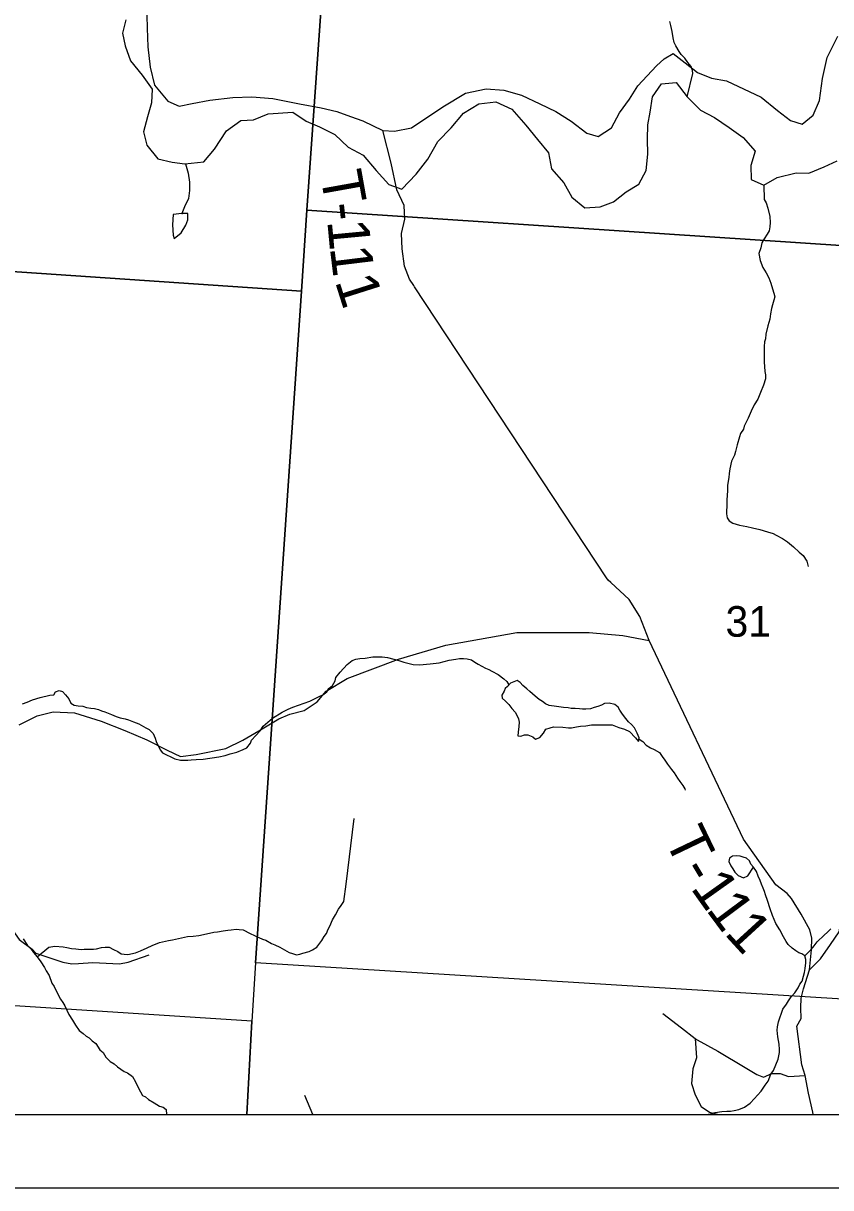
# Model space of a CAD drawing. Extents: x 0 to 34, y 0 to 22.
# Drawn here: x 6.168 to 7.274, y 14 to 15.594 of the extents above; entities that cross this region are included whole.
import ezdxf

# ---------------------------------------------------------------- set-up
doc = ezdxf.new("R2010")
doc.units = 0
for name, color, linetype in [('GM_X_Corporation', 7, 'Continuous'), ('GM_X_County_Road', 7, 'Continuous'), ('GM_X_Major_River', 7, 'Continuous'), ('GM_X_Minor_Lake', 7, 'Continuous'), ('GM_X_Minor_River', 7, 'Continuous'), ('GM_X_Section_Text', 7, 'Continuous'), ('GM_X_Township_Road', 7, 'Continuous'), ('GM_X_Township_Road_Text', 7, 'Continuous'), ('SH_Data', 7, 'Continuous')]:
    doc.layers.add(name, color=color, linetype=linetype)

msp = doc.modelspace()

# ---------------------------------------------------------------- linework, layer by layer
at = {"layer": 'GM_X_Corporation'}
for points in [[(3.3441, 14.1), (8.9, 14.1), (8.9, 20.9), (2.1, 20.9), (2.1, 16.1353), (2.1457, 16.065), (2.3447, 15.6926), (2.4297, 15.5215), (2.465, 15.4504), (2.4884, 15.4033), (2.5769, 15.2135), (2.7849, 14.8403), (2.8931, 14.6544), (3.0297, 14.4867), (3.1386, 14.3654), (3.228, 14.2415)], [(6.6272, 16.3394), (7.7202, 16.2762), (7.66, 15.265), (6.5568, 15.3381), (6.621, 16.2504)], [(5.4627, 14.1), (8.9, 14.1), (8.9, 16.2015), (7.873, 16.2628), (7.7162, 16.2721), (7.5782, 16.28), (6.6249, 16.3344), (6.6163, 16.2457), (5.9321, 16.289), (5.8351, 16.2952), (5.6497, 16.3069), (5.6022, 16.3258), (5.5809, 15.9822), (5.4893, 14.5091), (5.4833, 14.4122), (5.4763, 14.3006)], [(5.6072, 16.3154), (5.612, 16.3148), (6.621, 16.2504), (6.5568, 15.3381), (6.5491, 15.2271), (5.5415, 15.2956)], [(6.5568, 15.3381), (7.66, 15.265), (7.6002, 14.2387), (6.4864, 14.308), (6.5491, 15.2271)], [(5.5415, 15.2956), (6.5491, 15.2271), (6.4864, 14.308), (6.4814, 14.2281), (5.4795, 14.2928)], [(6.4745, 14.1), (7.5926, 14.1), (7.6002, 14.2387), (6.4864, 14.308), (6.4814, 14.2281)], [(5.4686, 14.1), (6.4745, 14.1), (6.4814, 14.2281), (5.4795, 14.2928)]]:
    msp.add_lwpolyline(points, close=True, dxfattribs=at)
at = {"layer": 'GM_X_County_Road'}
for points in [[(6.337, 15.6215), (6.3381, 15.5869), (6.3388, 15.5615), (6.3422, 15.5334), (6.3479, 15.5091), (6.3665, 15.487), (6.3817, 15.4802), (6.3995, 15.484), (6.4239, 15.4885), (6.4554, 15.4919), (6.4812, 15.4931), (6.5101, 15.4908), (6.5465, 15.4835), (6.5761, 15.4778), (6.5978, 15.4729), (6.6164, 15.466), (6.6331, 15.4603), (6.6604, 15.447), (6.6768, 15.4459), (6.6999, 15.4504)], [(6.6999, 15.4504), (6.7429, 15.4793), (6.7737, 15.4979), (6.8022, 15.5039), (6.8261, 15.502), (6.8504, 15.4955), (6.8754, 15.4834), (6.8975, 15.4731), (6.9183, 15.4598), (6.94, 15.4435), (6.9552, 15.4385), (6.9738, 15.4507), (6.9844, 15.4712), (6.9981, 15.4898), (7.0095, 15.508), (7.0225, 15.5217), (7.035, 15.5353), (7.0456, 15.5448), (7.0582, 15.5524), (7.0745, 15.5395), (7.0912, 15.5262), (7.1106, 15.5186), (7.1311, 15.5148), (7.1785, 15.4924), (7.2009, 15.4745), (7.2184, 15.4608), (7.2347, 15.4555), (7.2495, 15.4677), (7.2583, 15.4878), (7.2625, 15.5181), (7.269, 15.547), (7.2834, 15.5759)]]:
    msp.add_lwpolyline(points, dxfattribs=at)
at = {"layer": 'GM_X_Major_River'}
for points in [[(6.3087, 15.5985), (6.3041, 15.5803), (6.3078, 15.5628), (6.3153, 15.5423), (6.3311, 15.5226), (6.3447, 15.5036), (6.3439, 15.4846), (6.3385, 15.4657), (6.3332, 15.4452), (6.3376, 15.427), (6.3527, 15.408), (6.3724, 15.4034), (6.3898, 15.4011), (6.4155, 15.404), (6.43, 15.4214), (6.4467, 15.4464), (6.4664, 15.4608), (6.4838, 15.4615), (6.5036, 15.4697), (6.5376, 15.4719), (6.5557, 15.4597), (6.5739, 15.4521), (6.5951, 15.4414), (6.6132, 15.4239), (6.6336, 15.4132), (6.6517, 15.392), (6.669, 15.373), (6.6864, 15.3668), (6.7062, 15.3873), (6.7221, 15.4077), (6.7358, 15.4319), (6.754, 15.4508), (6.7708, 15.4705), (6.792, 15.4833), (6.8155, 15.4863), (6.8374, 15.4763), (6.8562, 15.4543), (6.8721, 15.4345), (6.8872, 15.4163), (6.8916, 15.3943), (6.9082, 15.3753), (6.9195, 15.3555), (6.9369, 15.3411), (6.9581, 15.3425), (6.9763, 15.3493), (6.9937, 15.3629), (7.0112, 15.3735), (7.0211, 15.3924), (7.0234, 15.4144)], [(7.0234, 15.4144), (7.0227, 15.4349), (7.0235, 15.4546), (7.0266, 15.472), (7.0297, 15.4932), (7.0419, 15.5106), (7.0623, 15.5128), (7.0774, 15.4931), (7.0955, 15.4748), (7.1144, 15.4649), (7.1348, 15.4512), (7.1537, 15.4375), (7.1703, 15.4185), (7.1642, 15.3988), (7.1649, 15.3798), (7.1822, 15.3722), (7.2004, 15.3828), (7.2262, 15.3888), (7.2436, 15.3887), (7.2648, 15.397), (7.2823, 15.4053)]]:
    msp.add_lwpolyline(points, dxfattribs=at)
at = {"layer": 'GM_X_Minor_Lake'}
for points in [[(6.3855, 15.3332), (6.3738, 15.332), (6.3727, 15.318), (6.3738, 15.3036), (6.3749, 15.2991)], [(6.3749, 15.2991), (6.3844, 15.3067), (6.3908, 15.3173), (6.3935, 15.3248), (6.3935, 15.3332), (6.3855, 15.3332)]]:
    msp.add_lwpolyline(points, dxfattribs=at)
at = {"layer": 'GM_X_Minor_River'}
msp.add_line((6.5646, 14.1), (6.554, 14.1262), dxfattribs=at)
for points in [[(7.0774, 15.4931), (7.0851, 15.5248), (7.0847, 15.529), (7.0826, 15.5347), (7.0781, 15.5398), (7.0741, 15.5459), (7.0688, 15.5509), (7.0663, 15.5551), (7.0615, 15.5628), (7.0593, 15.5674), (7.0579, 15.5739), (7.0565, 15.5823), (7.0548, 15.5907), (7.0534, 15.596)], [(6.3906, 15.4012), (6.3942, 15.3885), (6.3961, 15.376), (6.3961, 15.3646), (6.3946, 15.354), (6.3893, 15.3426), (6.3855, 15.3332), (6.3863, 15.3332)], [(7.1822, 15.3722), (7.1828, 15.3527), (7.1853, 15.3481), (7.1875, 15.3404), (7.1903, 15.3294), (7.1909, 15.321), (7.1904, 15.3149), (7.1896, 15.3096), (7.1869, 15.3051), (7.1826, 15.2987), (7.1794, 15.2931), (7.1778, 15.2863), (7.1754, 15.2787), (7.1771, 15.2692), (7.1807, 15.2593), (7.1852, 15.252), (7.1888, 15.2455), (7.1917, 15.2378), (7.1942, 15.2302), (7.196, 15.2245), (7.1971, 15.2191), (7.1959, 15.2146), (7.1939, 15.2082), (7.1926, 15.2033), (7.1914, 15.1961), (7.1905, 15.1889), (7.1877, 15.1794), (7.1848, 15.1684), (7.1843, 15.162), (7.1831, 15.1575), (7.1826, 15.1514), (7.1824, 15.137), (7.1826, 15.1305), (7.1835, 15.1172), (7.1842, 15.1126), (7.1845, 15.1069), (7.1817, 15.0986), (7.1777, 15.0884), (7.1738, 15.079), (7.1687, 15.0715), (7.1648, 15.0628), (7.1608, 15.053), (7.1553, 15.0421), (7.1545, 15.038), (7.1502, 15.0323), (7.1486, 15.0278), (7.1454, 15.0165), (7.1434, 15.0074), (7.1418, 15.0025), (7.1378, 14.9942), (7.1357, 14.984), (7.1345, 14.9775), (7.134, 14.9722), (7.1323, 14.9616), (7.1322, 14.9537), (7.1316, 14.9415), (7.1315, 14.9366), (7.1309, 14.9222), (7.1319, 14.9168), (7.1345, 14.9126), (7.1397, 14.9095), (7.1488, 14.9067), (7.159, 14.905), (7.1665, 14.9033), (7.1767, 14.9009), (7.1873, 14.8977), (7.1948, 14.8952), (7.1989, 14.8933), (7.2075, 14.8886), (7.2147, 14.8839), (7.2225, 14.8773), (7.2307, 14.87), (7.2359, 14.8653), (7.2411, 14.8576), (7.2429, 14.85)], [(6.2046, 14.674), (6.2103, 14.6747), (6.2126, 14.6788), (6.2176, 14.6806), (6.2221, 14.679), (6.2262, 14.6744), (6.2306, 14.669), (6.2336, 14.6632), (6.238, 14.6605), (6.2437, 14.6597), (6.2498, 14.6592), (6.255, 14.6572), (6.2611, 14.6563), (6.266, 14.6559), (6.2713, 14.6546), (6.2754, 14.6527), (6.2799, 14.6511), (6.2893, 14.6475), (6.2954, 14.6451), (6.301, 14.6431), (6.3078, 14.6415), (6.3123, 14.6403), (6.3195, 14.6375), (6.3266, 14.6351), (6.3364, 14.6292), (6.3409, 14.6272), (6.3461, 14.6215), (6.349, 14.6153), (6.3504, 14.6108), (6.3559, 14.5993), (6.3592, 14.595), (6.3758, 14.5872), (6.3837, 14.5851), (6.3882, 14.585), (6.3935, 14.5853), (6.3981, 14.5856), (6.4049, 14.5859), (6.4148, 14.5865), (6.436, 14.5899), (6.4448, 14.5917), (6.4516, 14.5938), (6.4608, 14.5963), (6.4695, 14.5996), (6.4745, 14.6018), (6.4795, 14.6082), (6.4807, 14.6123), (6.4927, 14.6254), (6.497, 14.6318), (6.5097, 14.6426), (6.5227, 14.6507), (6.5311, 14.6551), (6.5376, 14.6577), (6.5609, 14.6657), (6.5735, 14.6723), (6.5784, 14.6745), (6.5838, 14.6786), (6.5865, 14.6831), (6.5919, 14.6875), (6.5954, 14.6939), (6.5963, 14.6981), (6.6021, 14.7056), (6.6117, 14.7161), (6.6187, 14.7216), (6.6236, 14.7234), (6.6293, 14.7245), (6.6365, 14.7247), (6.6468, 14.7268), (6.6596, 14.7266), (6.6672, 14.7257), (6.6823, 14.7217), (6.6894, 14.7193), (6.7023, 14.716), (6.7106, 14.7155), (6.7254, 14.7168), (6.7334, 14.7178), (6.7375, 14.7185), (6.7516, 14.722), (6.7607, 14.7234), (6.7657, 14.7244), (6.771, 14.7244), (6.7759, 14.7239), (6.7819, 14.7223), (6.7864, 14.7195), (6.7913, 14.7164), (6.801, 14.7109), (6.8059, 14.7093), (6.81, 14.707), (6.8187, 14.7023), (6.8262, 14.6965), (6.8303, 14.6926), (6.8332, 14.6882)], [(6.8442, 14.6468), (6.8464, 14.6418), (6.8471, 14.6372), (6.8466, 14.6312), (6.8457, 14.6236), (6.8452, 14.6183), (6.8494, 14.6178), (6.8547, 14.6196), (6.8593, 14.62), (6.8657, 14.6172), (6.8698, 14.6137), (6.8755, 14.6163), (6.8805, 14.6222), (6.8836, 14.6275), (6.8897, 14.6293), (6.8943, 14.6307), (6.9068, 14.6305), (6.9147, 14.6296), (6.9189, 14.6296), (6.9257, 14.6306), (6.9314, 14.6316), (6.9383, 14.6323), (6.9462, 14.6333), (6.9508, 14.6336), (6.9697, 14.6333), (6.9743, 14.6336), (6.9837, 14.63), (6.9912, 14.6276), (6.9984, 14.6244), (7.0065, 14.6155), (7.0106, 14.6105), (7.0115, 14.6155), (7.0089, 14.622), (7.0049, 14.6296), (7.0012, 14.6339), (6.9971, 14.6377), (6.993, 14.6424), (6.9886, 14.6481), (6.9852, 14.6535), (6.9827, 14.6577), (6.9782, 14.6612), (6.9703, 14.6632), (6.9642, 14.6626), (6.96, 14.6604), (6.955, 14.6586), (6.9497, 14.6571), (6.9447, 14.6553), (6.9387, 14.6551), (6.9341, 14.6548), (6.93, 14.6552), (6.9239, 14.6557), (6.9186, 14.6558), (6.9145, 14.6566), (6.908, 14.6571), (6.8982, 14.6584), (6.8884, 14.6601), (6.8831, 14.6621), (6.879, 14.6656), (6.8745, 14.6683), (6.8693, 14.6729), (6.8618, 14.6791), (6.8577, 14.6826), (6.8521, 14.6873), (6.8484, 14.6915), (6.8443, 14.6943), (6.8355, 14.6906), (6.8313, 14.6861), (6.8282, 14.6831)], [(6.8282, 14.6831), (6.8266, 14.6794), (6.8235, 14.6741), (6.8238, 14.6699), (6.8286, 14.6657), (6.8331, 14.6614), (6.8372, 14.656), (6.8416, 14.651), (6.8442, 14.6468)], [(6.1676, 14.6621), (6.1737, 14.6643), (6.181, 14.6679), (6.1916, 14.6708), (6.2046, 14.674)], [(7.0113, 14.614), (7.0114, 14.6139), (7.0167, 14.6108), (7.0211, 14.6058), (7.0271, 14.6019), (7.032, 14.5999), (7.0391, 14.5956), (7.0428, 14.5902), (7.0465, 14.5852), (7.0502, 14.5795), (7.0558, 14.5722), (7.0595, 14.5676), (7.0639, 14.5607), (7.0672, 14.556), (7.0713, 14.5503), (7.0742, 14.5457), (7.0746, 14.5443)], [(6.1873, 14.3162), (6.2034, 14.3292), (6.2118, 14.3306), (6.2231, 14.3296), (6.228, 14.3288), (6.2345, 14.3276), (6.2405, 14.3271), (6.2477, 14.3262), (6.2519, 14.3265), (6.2583, 14.3264), (6.2647, 14.3267), (6.2689, 14.327), (6.2754, 14.3288), (6.2807, 14.329), (6.286, 14.329), (6.292, 14.3262), (6.298, 14.3231), (6.3025, 14.3203), (6.3067, 14.3195), (6.3116, 14.3194), (6.3222, 14.3215), (6.3291, 14.324), (6.3379, 14.3285), (6.3451, 14.3317), (6.355, 14.3354), (6.3672, 14.3382), (6.3729, 14.3392), (6.3931, 14.3438), (6.401, 14.3441), (6.4086, 14.3451), (6.4193, 14.3476), (6.4295, 14.3497), (6.4341, 14.35), (6.4421, 14.3517), (6.4485, 14.3524), (6.4531, 14.3531), (6.4599, 14.3537), (6.4641, 14.3536), (6.4694, 14.3528), (6.4791, 14.3477), (6.4851, 14.3453), (6.4957, 14.3402), (6.5005, 14.3386), (6.508, 14.3343), (6.5129, 14.3323), (6.5197, 14.3292), (6.5324, 14.3217), (6.537, 14.3205), (6.5426, 14.3189), (6.5468, 14.3196), (6.551, 14.321), (6.5597, 14.3235), (6.5643, 14.3254), (6.5701, 14.3294), (6.5771, 14.3384), (6.5802, 14.3437), (6.5833, 14.3478), (6.586, 14.3538), (6.588, 14.358), (6.5916, 14.3667), (6.5959, 14.3734), (6.5998, 14.381), (6.6037, 14.3862), (6.6072, 14.3918), (6.6106, 14.4153), (6.6213, 14.5055)], [(7.2083, 14.2442), (7.213, 14.2513), (7.2157, 14.2558), (7.2196, 14.2614), (7.2246, 14.2667), (7.2289, 14.2734), (7.2313, 14.2787), (7.2348, 14.2828), (7.2364, 14.2893), (7.238, 14.2945), (7.2388, 14.3002), (7.2394, 14.3078), (7.2394, 14.3124), (7.2384, 14.3173), (7.2343, 14.32), (7.2301, 14.3216), (7.226, 14.324), (7.2208, 14.3279), (7.2156, 14.3329), (7.2126, 14.3371), (7.2089, 14.3433), (7.2038, 14.3528), (7.1986, 14.3617), (7.1939, 14.3724), (7.191, 14.3815), (7.1871, 14.393), (7.1846, 14.401), (7.1831, 14.4052), (7.1813, 14.4098), (7.1791, 14.4155), (7.1773, 14.4205), (7.1744, 14.4266), (7.1719, 14.4327), (7.1678, 14.4385), (7.1645, 14.4427), (7.1623, 14.4473), (7.1582, 14.4508), (7.154, 14.4524), (7.1499, 14.4536), (7.1442, 14.4541), (7.1393, 14.4538), (7.1351, 14.4512), (7.1342, 14.4463), (7.1368, 14.4406), (7.1397, 14.4363), (7.1423, 14.4317), (7.1468, 14.4271), (7.1543, 14.4239), (7.16, 14.4269), (7.1678, 14.4385)], [(7.2384, 14.3173), (7.2469, 14.3259), (7.2508, 14.3312), (7.255, 14.3364), (7.2646, 14.3457), (7.2693, 14.3498), (7.2739, 14.3543)], [(6.1684, 14.3408), (6.1743, 14.3316), (6.1791, 14.3266), (6.1825, 14.322), (6.1873, 14.3162), (6.1925, 14.3093), (6.1973, 14.3012), (6.1998, 14.2966), (6.2039, 14.2905), (6.2075, 14.2798), (6.2108, 14.2752), (6.2137, 14.2687), (6.2196, 14.2579), (6.2226, 14.2537), (6.2255, 14.2487), (6.228, 14.243), (6.231, 14.2369), (6.2358, 14.2292), (6.2398, 14.2223), (6.245, 14.215), (6.2506, 14.2111), (6.2547, 14.2076), (6.2588, 14.2052), (6.2629, 14.201), (6.2678, 14.1975), (6.2733, 14.1887), (6.2778, 14.1852), (6.2815, 14.1787), (6.2874, 14.1729), (6.293, 14.1697), (6.2975, 14.1655), (6.3065, 14.1589), (6.311, 14.1573), (6.3181, 14.1522), (6.3221, 14.1449), (6.3262, 14.1361), (6.3291, 14.1311), (6.3317, 14.1262), (6.3358, 14.1242), (6.3399, 14.1207), (6.3478, 14.116), (6.3549, 14.1117), (6.3598, 14.1101), (6.3639, 14.107), (6.3645, 14.1)], [(7.105, 14.1), (7.1062, 14.1005), (7.1107, 14.1015), (7.1153, 14.103), (7.1244, 14.1043), (7.1316, 14.1046), (7.1365, 14.1049), (7.1415, 14.1059), (7.1479, 14.107), (7.1556, 14.1103), (7.1633, 14.1158), (7.1694, 14.1222), (7.1733, 14.1267), (7.1783, 14.1323), (7.1838, 14.1402), (7.188, 14.1458), (7.1916, 14.1552), (7.1955, 14.1605), (7.1986, 14.1684), (7.2018, 14.1759), (7.2035, 14.185), (7.2036, 14.1892), (7.2029, 14.1964), (7.2012, 14.2067), (7.2002, 14.2154), (7.2007, 14.2204), (7.2023, 14.2272), (7.2083, 14.2442)]]:
    msp.add_lwpolyline(points, dxfattribs=at)
at = {"layer": 'GM_X_Township_Road'}
for points in [[(6.703, 15.2346), (6.6971, 15.2435), (6.6903, 15.2613), (6.6869, 15.2849), (6.6861, 15.3058), (6.6907, 15.3255), (6.69, 15.3441), (6.6797, 15.3658), (6.6718, 15.4022), (6.6604, 15.447)], [(6.9669, 14.8346), (6.7041, 15.233), (6.703, 15.2346)], [(7.0251, 14.7489), (7.0123, 14.7817), (6.9979, 14.8052), (6.9727, 14.8281), (6.9691, 14.8314), (6.9669, 14.8346)], [(6.7801, 14.7484), (6.8441, 14.7597), (6.9432, 14.7597), (6.9889, 14.7559), (7.0251, 14.7489)], [(6.1629, 14.6336), (6.1873, 14.6457), (6.2093, 14.6514), (6.2385, 14.6499), (6.275, 14.6385), (6.3076, 14.6259), (6.3376, 14.613), (6.3653, 14.599), (6.3836, 14.5902), (6.4052, 14.5929), (6.4455, 14.6012), (6.469, 14.6126), (6.4911, 14.6255), (6.5184, 14.6418), (6.5333, 14.6479), (6.553, 14.6532), (6.5709, 14.6649), (6.583, 14.6797), (6.6117, 14.6969), (6.6822, 14.7235), (6.747, 14.7426), (6.7801, 14.7484)], [(7.2447, 14.298), (7.2475, 14.3254), (7.2478, 14.3415), (7.2451, 14.3528), (7.2334, 14.3746), (7.2198, 14.3959), (7.2139, 14.4027), (7.1985, 14.4147), (7.1541, 14.4769), (7.0251, 14.7489)], [(7.2447, 14.298), (7.2598, 14.3134), (7.2735, 14.3329), (7.2854, 14.3504), (7.2885, 14.3675), (7.2967, 14.3791), (7.3084, 14.3921), (7.3234, 14.4048), (7.3344, 14.4167), (7.3453, 14.4287), (7.3545, 14.4479), (7.3665, 14.4776), (7.3734, 14.4978), (7.3775, 14.5081), (7.3846, 14.5228), (7.3976, 14.5426), (7.4076, 14.5614), (7.4202, 14.5833), (7.4298, 14.6032), (7.4356, 14.6151), (7.4425, 14.6398), (7.4445, 14.6541), (7.4503, 14.6726), (7.4505, 14.6734)], [(6.0588, 14.4412), (6.0875, 14.4342), (6.1024, 14.4238), (6.1139, 14.4079), (6.1253, 14.3921), (6.1629, 14.3396), (6.1808, 14.3267), (6.1858, 14.3208), (6.2225, 14.3089), (6.2349, 14.3064), (6.2439, 14.3068), (6.2637, 14.3083), (6.3, 14.3063), (6.3122, 14.3085), (6.3407, 14.3187)], [(7.2497, 14.1), (7.2492, 14.1033), (7.2433, 14.1295), (7.2387, 14.1538), (7.2343, 14.1684), (7.2275, 14.2212), (7.2334, 14.2317), (7.2328, 14.2464), (7.2334, 14.2594), (7.2362, 14.272), (7.2447, 14.298)], [(7.0437, 14.2383), (7.0692, 14.219), (7.0883, 14.2042), (7.0908, 14.2023), (7.1193, 14.1867), (7.1565, 14.1646), (7.1724, 14.1548), (7.1815, 14.1513), (7.1929, 14.1563), (7.2043, 14.1563), (7.2161, 14.1521), (7.2387, 14.1538)], [(7.0883, 14.2042), (7.09, 14.1776), (7.0851, 14.1628), (7.0832, 14.1426), (7.0881, 14.1271), (7.0964, 14.1111), (7.1078, 14.1035), (7.1205, 14.1)]]:
    msp.add_lwpolyline(points, dxfattribs=at)
at = {"layer": 'SH_Data'}
for p, q in [((2.1, 14.1), (8.9, 14.1)), ((2, 14), (9, 14))]:
    msp.add_line(p, q, dxfattribs=at)

# ---------------------------------------------------------------- texts
at = {"layer": 'GM_X_Section_Text'}
msp.add_text('31', height=0.04186, rotation=0, dxfattribs=at).set_placement((7.1297, 14.7541))
at = {"layer": 'GM_X_Township_Road_Text'}
for s, rotation, p in [('T', 280.1672, (6.5746, 15.3871)), ('-', 276.3357, (6.582, 15.3463)), ('1', 275.3575, (6.5845, 15.3233)), ('1', 276.9768, (6.588, 15.2868)), ('1', 287.6091, (6.5947, 15.2408)), ('T', 295.6158, (7.0452, 14.4776)), ('-', 301.0279, (7.0663, 14.4341)), ('1', 305.4214, (7.0809, 14.4101)), ('1', 306.6852, (7.102, 14.3805)), ('1', 312.4775, (7.1269, 14.3476))]:
    msp.add_text(s, height=0.0568, rotation=rotation, dxfattribs=at).set_placement(p)

doc.saveas('drawing.dxf')
